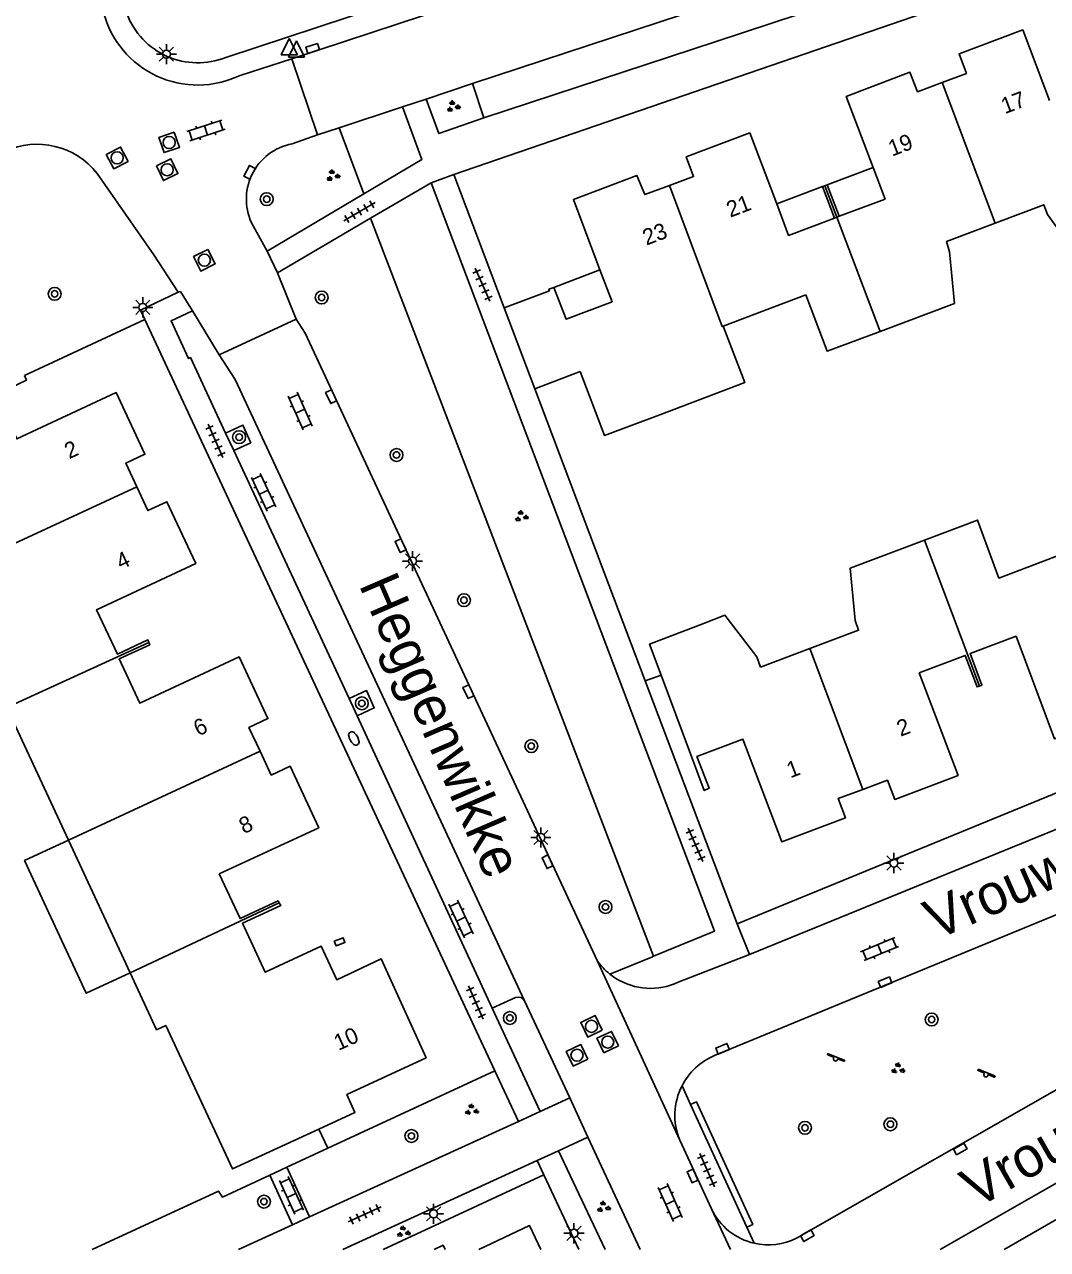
# Model space of a CAD drawing. Extents: x 136000 to 138005, y 398500 to 400500.
# Drawn here: x 137398.5 to 137462, y 398500 to 398576 of the extents above; entities that cross this region are included whole.
import ezdxf

# ---------------------------------------------------------------- set-up
doc = ezdxf.new("R2010")
doc.units = 0
for name, color, linetype in [('gg-afsc-erfafscheiding', 7, 'Continuous'), ('gg-afsc-hekwerk', 7, 'Continuous'), ('gg-afsc-muur', 7, 'Continuous'), ('gg-anno-huisnummerreeks BGT', 7, 'Continuous'), ('gg-anno-openbare ruimte label', 7, 'Continuous'), ('gg-bbg-hoofdgebouw', 7, 'Continuous'), ('gg-bbg-luifel en loopbrug', 7, 'Continuous'), ('gg-bbg-tussenscheiding', 7, 'Continuous'), ('gg-knt-verharding', 7, 'Continuous'), ('gt-grn-groengrens', 7, 'Continuous'), ('gt-grn-vlakafsluiter', 7, 'Continuous'), ('gt-grn-weggrens', 7, 'Continuous'), ('gt-symb-boom', 7, 'Continuous'), ('gt-symb-brandkraan', 7, 'Continuous'), ('gt-symb-groenvak', 7, 'Continuous'), ('gt-symb-klinker verharding', 7, 'Continuous'), ('gt-symb-kolk', 7, 'Continuous'), ('gt-symb-lichtmast', 7, 'Continuous'), ('gt-symb-rioolschacht', 7, 'Continuous'), ('gt-symb-speelvoorziening', 7, 'Continuous'), ('gt-symb-tegel verharding', 7, 'Continuous'), ('gt-symb-waterafsluiter', 7, 'Continuous')]:
    doc.layers.add(name, color=color, linetype=linetype)

# ---------------------------------------------------------------- blocks, each defined once
blk = doc.blocks.new('gt0-RS')
at = {"layer": 'gt-symb-rioolschacht'}
blk.add_lwpolyline([(-0.5, -0.5), (0.5, -0.5), (0.5, 0.5), (-0.5, 0.5)], close=True, dxfattribs=at)
blk.add_circle((0, 0), 0.375, dxfattribs=at)
blk = doc.blocks.new('gt0-KL1')
at = {"layer": 'gt-symb-klinker verharding'}
for p, q in [((-1.15, 0.3), (1.15, 0.3)), ((-1, -0.3), (-1, 0.3)), ((-0.5, 0.3), (-0.5, 0.45)), ((0, -0.3), (0, 0.3)), ((0.5, 0.3), (0.5, 0.45)), ((1, -0.3), (1, 0.3)), ((-1.15, -0.3), (1.15, -0.3)), ((-0.5, -0.45), (-0.5, -0.3)), ((0.5, -0.45), (0.5, -0.3))]:
    blk.add_line(p, q, dxfattribs=at)
blk = doc.blocks.new('gt0-LMAST')
at = {"layer": 'gt-symb-lichtmast'}
for p, q in [((-0.182, 0.173), (-0.447, 0.438)), ((-0.005, 0.246), (-0.005, 0.621)), ((0.172, 0.173), (0.437, 0.438)), ((-0.255, -0.004), (-0.63, -0.004)), ((-0.182, -0.181), (-0.447, -0.446)), ((-0.005, -0.254), (-0.005, -0.629)), ((0.437, -0.446), (0.172, -0.181)), ((0.245, -0.004), (0.62, -0.004))]:
    blk.add_line(p, q, dxfattribs=at)
blk.add_circle((-0.005, -0.004), 0.25, dxfattribs=at)
blk = doc.blocks.new('gt0-WAFSL')
at = {"layer": 'gt-symb-waterafsluiter'}
for p, q in [((-0.5, -0.333), (0, 0.667)), ((0, 0.667), (0.5, -0.333)), ((0.5, -0.333), (-0.5, -0.333))]:
    blk.add_line(p, q, dxfattribs=at)
blk = doc.blocks.new('gt0-KOLK')
at = {"layer": 'gt-symb-kolk'}
blk.add_lwpolyline([(0, 0), (0.375, 0), (0.375, 0.4), (-0.375, 0.4), (-0.375, 0), (0, 0)], dxfattribs=at)
blk = doc.blocks.new('gt0-GRVAK')
at = {"layer": 'gt-symb-groenvak'}
for p, q in [((-0.11, 0.189), (-0.228, 0.24)), ((-0.182, 0.153), (0.088, 0.153)), ((-0.091, 0.211), (-0.156, 0.322)), ((-0.047, 0.214), (-0.047, 0.393)), ((-0.004, 0.211), (0.061, 0.322)), ((0.015, 0.189), (0.133, 0.24)), ((0.262, -0.052), (0.197, 0.059)), ((0.305, -0.049), (0.305, 0.13)), ((0.349, -0.052), (0.414, 0.059)), ((-0.245, -0.228), (-0.363, -0.177)), ((-0.318, -0.264), (-0.047, -0.264)), ((-0.226, -0.206), (-0.291, -0.095)), ((-0.183, -0.203), (-0.183, -0.024)), ((-0.139, -0.206), (-0.074, -0.095)), ((-0.12, -0.228), (-0.002, -0.177)), ((0.243, -0.074), (0.125, -0.023)), ((0.17, -0.11), (0.441, -0.11)), ((0.368, -0.074), (0.486, -0.023))]:
    blk.add_line(p, q, dxfattribs=at)
blk = doc.blocks.new('gt0-TEG1')
at = {"layer": 'gt-symb-tegel verharding'}
for p, q in [((-1.125, 0), (1.125, 0)), ((-0.9, -0.25), (-0.9, 0.25)), ((-0.45, -0.25), (-0.45, 0.25)), ((0, -0.25), (0, 0.25)), ((0.45, -0.25), (0.45, 0.25)), ((0.9, -0.25), (0.9, 0.25))]:
    blk.add_line(p, q, dxfattribs=at)
blk = doc.blocks.new('gt0-BOOM')
at = {"layer": 'gt-symb-boom'}
for radius in [0.4, 0.2]:
    blk.add_circle((0, 0), radius, dxfattribs=at)
blk = doc.blocks.new('gt0-BR')
at = {"layer": 'gt-symb-brandkraan'}
for centre, radius, start, end in [((-0.244, 0), 0.206, 107.56694, 252.43307), ((0.599, -2.664), 3, 106.89205, 107.56694), ((0, -0.691), 0.938, 73.10799, 106.89205), ((-0.599, -2.664), 3, 72.43309, 73.10799), ((0.244, 0), 0.206, 287.56695, 72.43309), ((0.599, 2.664), 3, 252.43307, 253.10797), ((0, 0.691), 0.938, 253.10797, 286.89206), ((-0.599, 2.664), 3, 286.89206, 287.56695)]:
    blk.add_arc(centre, radius, start, end, dxfattribs=at)
blk = doc.blocks.new('gt0-SV')
at = {"layer": 'gt-symb-speelvoorziening'}
for p, q in [((-0.477, 0.255), (-0.08, 0.096)), ((0.542, -0.076), (-0.449, 0.324)), ((0.125, 0.014), (0.515, -0.143))]:
    blk.add_line(p, q, dxfattribs=at)
for centre, radius, start, end in [((-0.466, 0.291), 0.0369, 63.6251, 252.66016), ((-0.002, -0.005), 0.128, 127.68665, 8.59861), ((0.531, -0.111), 0.0363, 243.50852, 72.54358)]:
    blk.add_arc(centre, radius, start, end, dxfattribs=at)

msp = doc.modelspace()

# ---------------------------------------------------------------- linework, layer by layer
at = {"layer": 'gg-afsc-erfafscheiding'}
for p, q in [((137416.796, 398507.472), (137417.349, 398506.279)), ((137417.349, 398506.279), (137414.814, 398505.103)), ((137414.814, 398505.103), (137413.753, 398504.611))]:
    msp.add_line(p, q, dxfattribs=at)
msp.add_lwpolyline([(137402.725, 398500), (137410.577, 398503.626), (137410.816, 398503.248), (137413.753, 398504.611)], dxfattribs=at)
at = {"layer": 'gg-afsc-hekwerk'}
msp.add_line((137428.291, 398558.421), (137425.16, 398566.699), dxfattribs=at)
at = {"layer": 'gg-afsc-muur'}
for p, q in [((137448.775, 398563.986), (137448.037, 398565.941)), ((137448.33, 398566.052), (137449.068, 398564.097)), ((137430.188, 398553.404), (137433.964, 398543.42)), ((137434.5, 398542.002), (137433.964, 398543.42)), ((137434.5, 398542.002), (137433.964, 398543.42)), ((137437.045, 398535.273), (137434.5, 398542.002)), ((137437.045, 398535.273), (137434.5, 398542.002)), ((137438.024, 398535.639), (137437.045, 398535.273)), ((137438.024, 398535.639), (137437.045, 398535.273))]:
    msp.add_line(p, q, dxfattribs=at)
msp.add_lwpolyline([(137417.75, 398519.136), (137417.863, 398518.841), (137418.408, 398519.051), (137418.294, 398519.345), (137417.75, 398519.136)], dxfattribs=at)
at = {"layer": 'gg-bbg-hoofdgebouw'}
for p, q in [((137448.775, 398563.986), (137448.925, 398564.043)), ((137448.925, 398564.043), (137449.068, 398564.097)), ((137441.881, 398557.283), (137446.997, 398559.23)), ((137428.291, 398558.421), (137430.188, 398553.404)), ((137433.01, 398554.47), (137430.188, 398553.404)), ((137444.197, 398536.124), (137447.249, 398537.277)), ((137397.437, 398533.623), (137401.266, 398525.39)), ((137401.266, 398525.39), (137405.092, 398517.166))]:
    msp.add_line(p, q, dxfattribs=at)
for points in [[(137455.463, 398572.391), (137456.962, 398572.949), (137456.508, 398574.171), (137460.452, 398575.665), (137462.108, 398571.291)], [(137451.173, 398567.126), (137449.507, 398571.536), (137453.458, 398573.032), (137453.936, 398571.822), (137455.463, 398572.391)], [(137438.538, 398566.007), (137440.041, 398566.56), (137439.585, 398567.791), (137443.527, 398569.275), (137445.193, 398564.867)], [(137449.068, 398564.097), (137451.912, 398565.171), (137451.173, 398567.126)], [(137434.233, 398560.768), (137432.583, 398565.139), (137436.523, 398566.626), (137437.009, 398565.444), (137438.538, 398566.007)], [(137445.193, 398564.867), (137445.931, 398562.912), (137448.775, 398563.986)], [(137463.894, 398561.576), (137461.983, 398564.21), (137461.753, 398564.817), (137458.754, 398563.677)], [(137458.754, 398563.677), (137455.735, 398562.53), (137455.902, 398561.898), (137456.217, 398558.692), (137451.616, 398556.962)], [(137434.233, 398560.768), (137434.978, 398558.796), (137432.125, 398557.719), (137431.38, 398559.691)], [(137431.38, 398559.691), (137431.062, 398559.571), (137431.096, 398559.482), (137428.291, 398558.421)], [(137451.616, 398556.962), (137448.321, 398555.723), (137446.997, 398559.23)], [(137437.948, 398551.779), (137443.213, 398553.783), (137441.881, 398557.283)], [(137405.513, 398547.306), (137404.825, 398548.784), (137406.005, 398549.334), (137404.222, 398553.159), (137398.058, 398550.287), (137396.77, 398553.052), (137398.665, 398553.935), (137398.53, 398554.225)], [(137437.948, 398551.779), (137434.51, 398550.502), (137433.01, 398554.47)], [(137406.259, 398537.652), (137406.194, 398537.819), (137404.301, 398536.934), (137403.013, 398539.688), (137409.164, 398542.565), (137407.375, 398546.39), (137406.196, 398545.841), (137405.513, 398547.306)], [(137454.362, 398544.007), (137457.655, 398545.25), (137458.98, 398541.651), (137464.175, 398543.644)], [(137447.249, 398537.277), (137450.268, 398538.418), (137450.061, 398539.026), (137449.758, 398542.268), (137454.362, 398544.007)], [(137438.024, 398535.639), (137437.307, 398537.562), (137440.723, 398538.851)], [(137444.197, 398536.124), (137443.953, 398536.769), (137441.978, 398539.347), (137440.723, 398538.851)], [(137467.447, 398534.941), (137465.922, 398534.363), (137466.363, 398533.153), (137462.433, 398531.676), (137460.041, 398538.041), (137457.186, 398536.968), (137457.921, 398535.012), (137457.773, 398534.956)], [(137413.15, 398530.913), (137412.46, 398532.389), (137413.638, 398532.938), (137411.85, 398536.765), (137405.698, 398533.891), (137404.416, 398536.636), (137406.31, 398537.52), (137406.259, 398537.652)], [(137457.773, 398534.956), (137457.627, 398534.901), (137456.886, 398536.855), (137454.034, 398535.774), (137456.445, 398529.416), (137452.518, 398527.927), (137452.057, 398529.116), (137450.529, 398528.547)], [(137450.529, 398528.547), (137449.007, 398527.981), (137449.458, 398526.777), (137445.512, 398525.286), (137443.093, 398531.651), (137440.242, 398530.582), (137441.007, 398528.615), (137440.698, 398528.472), (137438.024, 398535.639)], [(137414.334, 398521.512), (137414.27, 398521.629), (137411.907, 398520.526), (137410.619, 398523.302), (137416.787, 398526.164), (137415.017, 398529.979), (137413.843, 398529.432), (137413.15, 398530.913)], [(137416.796, 398507.472), (137419.033, 398508.506), (137418.54, 398509.61), (137423.447, 398511.899), (137420.663, 398518.024), (137417.906, 398516.74), (137416.939, 398518.815), (137413.475, 398517.202), (137412.06, 398520.238), (137414.43, 398521.335), (137414.334, 398521.512)], [(137405.092, 398517.166), (137406.734, 398513.635), (137407.298, 398513.898), (137411.449, 398505.002), (137416.796, 398507.472)], [(137426.715, 398500), (137429.87, 398501.488), (137430.572, 398500)], [(137423.953, 398500), (137424.498, 398500.263), (137424.621, 398500)]]:
    msp.add_lwpolyline(points, dxfattribs=at)
at = {"layer": 'gg-bbg-luifel en loopbrug'}
for p, q in [((137448.33, 398566.052), (137451.173, 398567.126)), ((137448.037, 398565.941), (137445.193, 398564.867)), ((137448.037, 398565.941), (137448.184, 398565.997)), ((137448.184, 398565.997), (137448.33, 398566.052)), ((137448.925, 398564.043), (137448.184, 398565.997)), ((137431.38, 398559.691), (137434.233, 398560.768))]:
    msp.add_line(p, q, dxfattribs=at)
msp.add_lwpolyline([(137401.266, 398525.39), (137398.546, 398524.125), (137402.372, 398515.901), (137405.092, 398517.166)], dxfattribs=at)
at = {"layer": 'gg-bbg-tussenscheiding'}
for p, q in [((137455.463, 398572.391), (137458.754, 398563.677)), ((137448.925, 398564.043), (137451.616, 398556.962)), ((137405.513, 398547.306), (137397.062, 398543.402)), ((137457.773, 398534.956), (137454.362, 398544.007)), ((137406.259, 398537.652), (137397.437, 398533.623)), ((137450.529, 398528.547), (137447.249, 398537.277)), ((137413.15, 398530.913), (137401.266, 398525.39)), ((137414.334, 398521.512), (137405.092, 398517.166))]:
    msp.add_line(p, q, dxfattribs=at)
msp.add_lwpolyline([(137438.538, 398566.007), (137441.813, 398557.257), (137441.881, 398557.283)], dxfattribs=at)
at = {"layer": 'gg-knt-verharding'}
for p, q in [((137513.796, 398607.926), (137411.018, 398573.951)), ((137426.33, 398572.328), (137440.788, 398577.095)), ((137441.429, 398574.946), (137427.027, 398570.201)), ((137411.905, 398572.844), (137415.111, 398573.873)), ((137415.111, 398573.873), (137416.706, 398569.144)), ((137426.33, 398572.328), (137423.443, 398571.373)), ((137427.027, 398570.201), (137426.33, 398572.328)), ((137421.976, 398570.887), (137418.057, 398569.591)), ((137423.443, 398571.373), (137421.976, 398570.887)), ((137416.706, 398569.144), (137415.141, 398568.599)), ((137418.057, 398569.591), (137416.706, 398569.144)), ((137420.008, 398563.985), (137423.754, 398566.183)), ((137413.597, 398561.946), (137419.581, 398565.491)), ((137414.228, 398560.594), (137420.008, 398563.985)), ((137412.718, 398563.509), (137413.597, 398561.946)), ((137413.597, 398561.946), (137414.228, 398560.594)), ((137414.228, 398560.594), (137415.383, 398557.711)), ((137405.739, 398558.277), (137408.074, 398559.387)), ((137398.53, 398554.225), (137406.011, 398557.7)), ((137406.011, 398557.7), (137405.739, 398558.277)), ((137427.719, 398511.09), (137406.011, 398557.7)), ((137408.951, 398558.238), (137410.615, 398555.499)), ((137415.383, 398557.711), (137410.615, 398555.499)), ((137415.383, 398557.711), (137415.945, 398556.847)), ((137415.945, 398556.847), (137434.056, 398517.924)), ((137411.014, 398550.647), (137411.518, 398549.563)), ((137411.518, 398549.563), (137418.673, 398534.184)), ((137442.743, 398520.208), (137437.045, 398535.273)), ((137418.673, 398534.184), (137419.176, 398533.105)), ((137419.176, 398533.105), (137427.548, 398514.967)), ((137475.04, 398525.92), (137441.332, 398512.027)), ((137443.512, 398518.301), (137442.743, 398520.208)), ((137437.558, 398518.195), (137437.487, 398518.166)), ((137443.512, 398518.301), (137439.088, 398516.583)), ((137446.425, 398500.697), (137478.164, 398518.835)), ((137437.487, 398518.166), (137434.846, 398517.083)), ((137435.217, 398516.82), (137434.846, 398517.083)), ((137428.994, 398515.64), (137427.548, 398514.967)), ((137432.355, 398509.417), (137429.56, 398515.43)), ((137455.328, 398500), (137481.998, 398515.261)), ((137427.548, 398514.967), (137430.528, 398508.569)), ((137459.306, 398500), (137483.146, 398513.721)), ((137429.183, 398507.946), (137427.719, 398511.09)), ((137439.851, 398509.002), (137439.322, 398510.157)), ((137432.355, 398509.417), (137430.528, 398508.569)), ((137432.355, 398509.417), (137433.484, 398506.966)), ((137443.343, 398501.383), (137439.851, 398509.002)), ((137416.223, 398502.021), (137429.183, 398507.946)), ((137431.668, 398506.121), (137433.484, 398506.966)), ((137433.484, 398506.966), (137436.727, 398500)), ((137439.176, 398506.788), (137441.154, 398502.516)), ((137431.668, 398506.121), (137434.55, 398500)), ((137418.28, 398500), (137430.341, 398505.523)), ((137430.341, 398505.523), (137430.759, 398504.625)), ((137415.159, 398501.534), (137413.753, 398504.611)), ((137416.223, 398502.021), (137414.814, 398505.103)), ((137430.759, 398504.625), (137432.911, 398500)), ((137411.803, 398500), (137415.159, 398501.534)), ((137415.159, 398501.534), (137416.223, 398502.021)), ((137443.801, 398500.383), (137443.343, 398501.383))]:
    msp.add_line(p, q, dxfattribs=at)
for points in [[(137415.111, 398573.873), (137470.907, 398592.259), (137516.356, 398607.287), (137529.699, 398611.734)], [(137441.429, 398574.946), (137492.856, 398591.909), (137492.152, 398594.032)], [(137425.16, 398566.699), (137462.487, 398579.529), (137462.894, 398578.337), (137466.061, 398579.479)], [(137419.581, 398565.491), (137423.188, 398567.627), (137421.976, 398570.887)], [(137427.027, 398570.201), (137424.237, 398569.235), (137423.443, 398571.373)], [(137408.074, 398559.387), (137406.551, 398561.704), (137403.051, 398566.763)], [(137423.754, 398566.183), (137441.33, 398519.741), (137437.558, 398518.195)], [(137408.951, 398558.238), (137408.206, 398559.428), (137408.074, 398559.387)], [(137411.014, 398550.647), (137408.827, 398555.334), (137408.719, 398555.271), (137407.63, 398557.607), (137408.951, 398558.238)], [(137410.615, 398555.499), (137411.614, 398553.979), (137429.56, 398515.43)], [(137411.014, 398550.647), (137412.083, 398551.145), (137412.573, 398550.054), (137411.518, 398549.563)], [(137485.241, 398536.065), (137479.89, 398535.437), (137442.743, 398520.208)], [(137418.673, 398534.184), (137419.743, 398534.682), (137420.236, 398533.598), (137419.176, 398533.105)], [(137443.512, 398518.301), (137480.288, 398533.308), (137485.169, 398534.022)]]:
    msp.add_lwpolyline(points, dxfattribs=at)
for centre, radius, start, end in [((137409.282, 398578.281), 6.037, 194.58564, 295.75683), ((137409.29, 398578.333), 4.71, 200.93254, 291.52649), ((137399.321, 398563.808), 4.758, 38.38327, 114.68364), ((137415.791, 398565.168), 3.492, 100.72878, 208.35939), ((137437.367, 398520.243), 4.043, 215.00425, 231.41374), ((137437.37, 398520.25), 4.05, 237.88731, 295.10562), ((137429.142, 398515.171), 0.492, 31.80371, 107.48409), ((137442.913, 398508.313), 4.037, 113.05293, 152.81412), ((137442.91, 398508.314), 4.033, 152.8083, 202.22884), ((137444.68, 398504.183), 3.9, 205.29935, 256.97567), ((137444.677, 398504.185), 3.901, 257.02622, 296.62144)]:
    msp.add_arc(centre, radius, start, end, dxfattribs=at)
at = {"layer": 'gt-grn-groengrens'}
for p, q in [((137419.581, 398565.491), (137418.057, 398569.591)), ((137437.558, 398518.195), (137420.008, 398563.985))]:
    msp.add_line(p, q, dxfattribs=at)
msp.add_lwpolyline([(137443.343, 398501.383), (137443.706, 398501.55), (137440.215, 398509.169), (137439.851, 398509.002)], dxfattribs=at)
at = {"layer": 'gt-grn-vlakafsluiter'}
for p, q in [((137427.719, 398511.09), (137417.349, 398506.279)), ((137420.793, 398500), (137430.759, 398504.625))]:
    msp.add_line(p, q, dxfattribs=at)
at = {"layer": 'gt-grn-weggrens'}
for p, q in [((137423.754, 398566.183), (137425.16, 398566.699)), ((137434.056, 398517.924), (137439.176, 398506.788)), ((137429.183, 398507.946), (137430.528, 398508.569)), ((137430.341, 398505.523), (137431.668, 398506.121)), ((137441.154, 398502.516), (137442.321, 398500))]:
    msp.add_line(p, q, dxfattribs=at)

# ---------------------------------------------------------------- block references
at = {"layer": 'gt-symb-boom'}
for p in [(137413.562, 398565.163), (137400.407, 398559.287), (137416.971, 398559.064), (137411.849, 398550.397), (137421.612, 398549.293), (137425.795, 398540.282), (137419.462, 398533.881), (137429.972, 398531.232), (137434.576, 398521.251), (137428.644, 398514.365), (137454.806, 398514.267), (137446.948, 398507.549), (137452.247, 398507.77), (137422.538, 398507.043), (137413.39, 398502.971)]:
    msp.add_blockref('gt0-BOOM', p, dxfattribs=at)
at = {"layer": 'gt-symb-brandkraan', "rotation": -60.71717142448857}
msp.add_blockref('gt0-BR', (137418.968, 398531.702), dxfattribs=at)
at = {"layer": 'gt-symb-groenvak'}
for p in [(137425.112, 398570.907), (137417.652, 398566.613)]:
    msp.add_blockref('gt0-GRVAK', p, dxfattribs=at)
for p, rotation in [((137429.346, 398545.468), -4.820766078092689), ((137452.705, 398511.201), -14.189180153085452), ((137426.259, 398508.651), -10.602058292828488), ((137434.44, 398502.62), -6.662963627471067), ((137422.027, 398501.08), -6.662963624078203)]:
    msp.add_blockref('gt0-GRVAK', p, dxfattribs=dict(at, rotation=rotation))
at = {"layer": 'gt-symb-klinker verharding'}
for p, rotation in [((137409.788, 398569.427), -161.81873102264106), ((137415.638, 398552.014), 114.00319025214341), ((137413.376, 398546.982), -65.02466534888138), ((137425.617, 398520.503), -65.02466534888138), ((137451.576, 398518.635), 22.386365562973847), ((137415.096, 398503.357), -65.40899949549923), ((137438.589, 398502.916), 114.00319025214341)]:
    msp.add_blockref('gt0-KL1', p, dxfattribs=dict(at, rotation=rotation))
at = {"layer": 'gt-symb-kolk'}
for p, rotation in [((137416.477, 398574.32), 18.12681251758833), ((137412.673, 398566.739), 63.25557979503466), ((137417.737, 398552.993), 114.9511516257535), ((137422.044, 398543.748), 114.9511516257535), ((137426.254, 398534.696), 114.9511516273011), ((137431.159, 398524.137), 114.9511516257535), ((137451.992, 398516.398), 22.386365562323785), ((137441.91, 398512.269), 22.333388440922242), ((137456.481, 398506.416), -150.38309020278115), ((137440.152, 398504.652), 114.59100050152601), ((137446.987, 398501.029), -149.4095645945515)]:
    msp.add_blockref('gt0-KOLK', p, dxfattribs=dict(at, rotation=rotation))
at = {"layer": 'gt-symb-lichtmast'}
for p in [(137407.346, 398574.16), (137405.88, 398558.451), (137422.612, 398542.712), (137430.57, 398525.564), (137452.467, 398523.978), (137423.916, 398502.217), (137432.623, 398501.007)]:
    msp.add_blockref('gt0-LMAST', p, dxfattribs=at)
at = {"layer": 'gt-symb-rioolschacht'}
for p, rotation in [((137407.51, 398568.679), -161.63753156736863), ((137404.285, 398567.722), -62.82026578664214), ((137407.39, 398566.987), -64.22889405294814), ((137409.694, 398561.376), -153.43494882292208), ((137433.709, 398513.843), 115.6678751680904), ((137434.712, 398512.868), 115.20722121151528), ((137432.809, 398512.05), 115.46334506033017)]:
    msp.add_blockref('gt0-RS', p, dxfattribs=dict(at, rotation=rotation))
at = {"layer": 'gt-symb-speelvoorziening'}
for p in [(137448.843, 398511.824), (137458.172, 398510.842)]:
    msp.add_blockref('gt0-SV', p, dxfattribs=at)
at = {"layer": 'gt-symb-tegel verharding'}
for p, rotation in [((137419.312, 398564.393), 30.206934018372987), ((137426.949, 398559.855), 114.00319025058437), ((137410.385, 398550.167), 114.00319025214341), ((137440.163, 398525.103), 114.00319025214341), ((137426.538, 398515.326), 114.00319025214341), ((137440.885, 398504.921), 114.0031902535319), ((137419.638, 398502.181), 24.591000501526)]:
    msp.add_blockref('gt0-TEG1', p, dxfattribs=dict(at, rotation=rotation))
at = {"layer": 'gt-symb-waterafsluiter'}
for p in [(137414.962, 398574.454), (137415.403, 398574.311)]:
    msp.add_blockref('gt0-WAFSL', p, dxfattribs=at)

# ---------------------------------------------------------------- texts
at = {"layer": 'gg-anno-huisnummerreeks BGT'}
for s, rotation, p in [('17', 20.7, (137459.34, 398570.432)), ('19', 20.7, (137452.343, 398567.798)), ('21', 20.6, (137442.307, 398564.008)), ('23', 20.7, (137437.109, 398562.275)), ('2', 25, (137401.308, 398549.022)), ('4', 25.1, (137404.511, 398542.154)), ('6', 25, (137409.316, 398531.823)), ('2', 20.8, (137452.875, 398531.806)), ('1', 20.7, (137446.04, 398529.227)), ('8', 24.9, (137412.137, 398525.761)), ('10', 24.5, (137418.011, 398512.315))]:
    msp.add_text(s, height=1, rotation=rotation, dxfattribs=at).set_placement(p)
at = {"layer": 'gg-anno-openbare ruimte label'}
for s, rotation, p in [('Heggenwikke', 293.4, (137419.254, 398541.245)), ('Vrouwenmantel', 23.8, (137455.074, 398519.17)), ('Vrouwenmantel', 29.8, (137457.587, 398502.514))]:
    msp.add_text(s, height=2.5, rotation=rotation, dxfattribs=at).set_placement(p)

doc.saveas('drawing.dxf')
